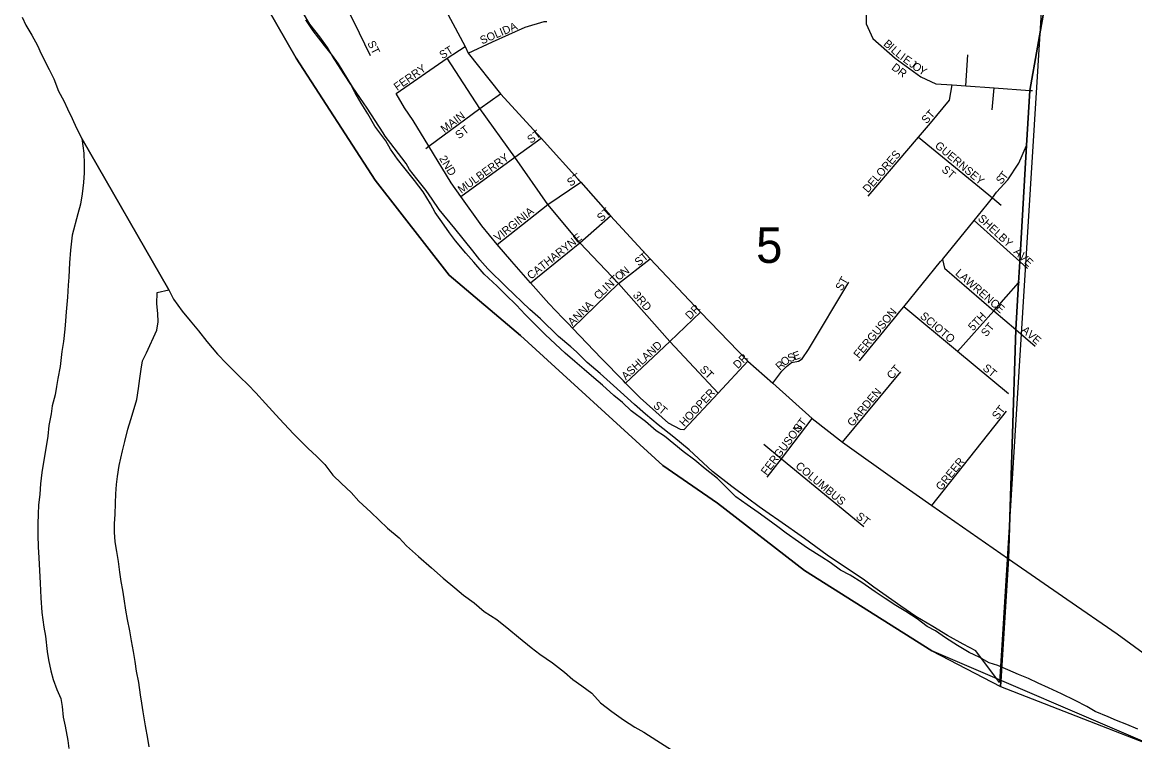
# Model space of a CAD drawing. Extents: x 1949938.81 to 1949945.61, y 152207.65 to 152214.09.
# Drawn here: x 1949940.07 to 1949941.387, y 152208.307 to 152209.158 of the extents above; entities that cross this region are included whole.
import ezdxf

# ---------------------------------------------------------------- set-up
doc = ezdxf.new("R2010")
doc.units = 0
for name, color, linetype in [('GM_X_City_Street', 7, 'Continuous'), ('GM_X_City_Street_Text', 7, 'Continuous'), ('GM_X_Corporation', 7, 'Continuous'), ('GM_X_County', 7, 'Continuous'), ('GM_X_Major_River', 7, 'Continuous'), ('GM_X_Section', 7, 'Continuous'), ('GM_X_Section_Text', 7, 'Continuous'), ('GM_X_Township', 7, 'Continuous')]:
    doc.layers.add(name, color=color, linetype=linetype)

msp = doc.modelspace()

# ---------------------------------------------------------------- linework, layer by layer
at = {"layer": 'GM_X_City_Street'}
for points in [[(1949940.4828, 152209.1185), (1949940.4627, 152209.1592), (1949940.4558, 152209.1732), (1949940.4287, 152209.2261), (1949940.4251, 152209.2332), (1949940.3975, 152209.2768), (1949940.3786, 152209.3094)], [(1949940.5424, 152209.2289), (1949940.5451, 152209.2227), (1949940.5948, 152209.1297), (1949940.5981, 152209.1219)], [(1949941.0694, 152209.1834), (1949941.0691, 152209.1566), (1949941.0772, 152209.1391), (1949941.1035, 152209.1159), (1949941.1339, 152209.0939), (1949941.1516, 152209.0857), (1949941.1711, 152209.0843), (1949941.1873, 152209.0832), (1949941.2206, 152209.0808), (1949941.2628, 152209.0777), (1949941.2661, 152209.0775)], [(1949940.5981, 152209.1219), (1949940.627, 152209.1354), (1949940.6657, 152209.1525), (1949940.6882, 152209.1592), (1949940.6913, 152209.1593)], [(1949940.5131, 152209.0739), (1949940.5732, 152209.1157), (1949940.5948, 152209.1297)], [(1949940.5981, 152209.1219), (1949940.6365, 152209.0736), (1949940.6848, 152209.0213), (1949940.7314, 152208.9693), (1949940.7666, 152208.9292), (1949940.8137, 152208.8783), (1949940.8731, 152208.8153), (1949940.9292, 152208.7573), (1949940.9589, 152208.7314), (1949941.0055, 152208.6895), (1949941.0412, 152208.6613), (1949941.1059, 152208.6151), (1949941.1469, 152208.5864), (1949941.2377, 152208.5233), (1949941.3066, 152208.4754), (1949941.3664, 152208.4347), (1949941.422, 152208.3939), (1949941.4607, 152208.3637)], [(1949940.8939, 152208.7194), (1949940.8368, 152208.7806), (1949940.776, 152208.8492), (1949940.7305, 152208.8974), (1949940.6924, 152208.9426), (1949940.6535, 152208.9988), (1949940.6119, 152209.0565), (1949940.5732, 152209.1157)], [(1949941.1873, 152209.0832), (1949941.1896, 152209.1198)], [(1949941.0715, 152208.9526), (1949941.1312, 152209.0225), (1949941.1454, 152209.0391), (1949941.1677, 152209.0662), (1949941.1711, 152209.0843)], [(1949940.7104, 152208.8083), (1949940.6938, 152208.8257), (1949940.6721, 152208.8501), (1949940.6497, 152208.8753), (1949940.6327, 152208.8955), (1949940.6142, 152208.9175), (1949940.5896, 152208.9521), (1949940.578, 152208.9684), (1949940.5518, 152209.0116), (1949940.5333, 152209.0422), (1949940.5229, 152209.0571), (1949940.5131, 152209.0739)], [(1949940.5483, 152209.009), (1949940.5518, 152209.0116), (1949940.6119, 152209.0565), (1949940.6365, 152209.0736)], [(1949941.2184, 152209.0549), (1949941.2206, 152209.0808)], [(1949940.5896, 152208.9521), (1949940.6535, 152208.9988), (1949940.6848, 152209.0213)], [(1949941.1312, 152209.0225), (1949941.2186, 152208.9506), (1949941.2291, 152208.942)], [(1949941.1582, 152208.876), (1949941.1594, 152208.8775), (1949941.197, 152208.9236), (1949941.2124, 152208.9425), (1949941.2186, 152208.9506), (1949941.2236, 152208.9572), (1949941.2371, 152208.9719), (1949941.2498, 152208.9915), (1949941.2592, 152209.0126)], [(1949940.6327, 152208.8955), (1949940.6924, 152208.9426), (1949940.7314, 152208.9693)], [(1949940.6721, 152208.8501), (1949940.7305, 152208.8974), (1949940.7666, 152208.9292)], [(1949941.197, 152208.9236), (1949941.251, 152208.8752), (1949941.26, 152208.8671)], [(1949940.7217, 152208.7964), (1949940.776, 152208.8492), (1949940.8137, 152208.8783)], [(1949941.1072, 152208.8136), (1949941.1138, 152208.8216), (1949941.1574, 152208.8751), (1949941.1582, 152208.876)], [(1949941.1594, 152208.8775), (1949941.1618, 152208.8672), (1949941.2203, 152208.817), (1949941.2462, 152208.7948), (1949941.2692, 152208.7751)], [(1949940.9589, 152208.7314), (1949940.9696, 152208.7456), (1949940.9749, 152208.7508), (1949940.9807, 152208.7555), (1949940.9893, 152208.7572), (1949940.9936, 152208.7599), (1949941.0011, 152208.7712), (1949941.0486, 152208.8506)], [(1949941.1773, 152208.7687), (1949941.2203, 152208.817), (1949941.2495, 152208.8499), (1949941.2508, 152208.8513)], [(1949941.2377, 152208.7185), (1949941.1773, 152208.7687), (1949941.1138, 152208.8216)], [(1949940.782, 152208.7338), (1949940.7559, 152208.7604), (1949940.7217, 152208.7964), (1949940.7168, 152208.8016), (1949940.7104, 152208.8083)], [(1949940.7845, 152208.7313), (1949940.8368, 152208.7806), (1949940.8731, 152208.8153)], [(1949941.0615, 152208.7575), (1949941.1063, 152208.8124), (1949941.1072, 152208.8136)], [(1949940.8535, 152208.6761), (1949940.8939, 152208.7194), (1949940.9292, 152208.7573)], [(1949941.0412, 152208.6613), (1949941.1103, 152208.7447)], [(1949940.8535, 152208.6761), (1949940.8497, 152208.6765), (1949940.8354, 152208.6839), (1949940.8016, 152208.7139), (1949940.785, 152208.7308), (1949940.7845, 152208.7313), (1949940.782, 152208.7338)], [(1949940.9521, 152208.6198), (1949940.9689, 152208.6418), (1949941.0055, 152208.6895)], [(1949941.1469, 152208.5864), (1949941.2354, 152208.6979)], [(1949940.9481, 152208.659), (1949940.9689, 152208.6418), (1949941.0663, 152208.5614)]]:
    msp.add_lwpolyline(points, dxfattribs=at)
at = {"layer": 'GM_X_Corporation'}
msp.add_lwpolyline([(1949942.1062, 152209.4059), (1949942.0896, 152209.1325), (1949942.3484, 152209.1187), (1949942.2928, 152208.2633), (1949942.1618, 152208.279), (1949942.0982, 152208.0722), (1949942.0477, 152208.0858), (1949941.8214, 152208.1567), (1949941.682, 152208.19), (1949941.6393, 152208.2075), (1949941.5072, 152208.2663), (1949941.4156, 152208.2992), (1949941.1468, 152208.4145), (1949940.9962, 152208.5094), (1949940.8932, 152208.5894), (1949940.8285, 152208.6338), (1949940.6601, 152208.7875), (1949940.5757, 152208.8589), (1949940.4882, 152208.9716), (1949940.3947, 152209.1158), (1949940.3383, 152209.2145)], dxfattribs=at)
at = {"layer": 'GM_X_County'}
msp.add_lwpolyline([(1949940.3383, 152209.2145), (1949940.3947, 152209.1158), (1949940.4882, 152208.9716), (1949940.5757, 152208.8589), (1949940.6601, 152208.7875), (1949940.8285, 152208.6338), (1949940.8932, 152208.5894), (1949940.9962, 152208.5094), (1949941.1468, 152208.4145), (1949941.2284, 152208.3724), (1949941.4156, 152208.2992), (1949941.5072, 152208.2663), (1949941.6393, 152208.2075), (1949941.682, 152208.19), (1949941.8214, 152208.1567), (1949941.9395, 152208.1188), (1949942.0477, 152208.0858), (1949942.1534, 152208.0573), (1949942.2476, 152208.0399), (1949942.3082, 152208.046), (1949942.5103, 152208.0107), (1949942.8268, 152208.0046)], dxfattribs=at)
at = {"layer": 'GM_X_Major_River'}
for p, q in [((1949940.1408, 152209.0207), (1949940.2439, 152208.8416)), ((1949940.2439, 152208.8416), (1949940.1408, 152209.0207))]:
    msp.add_line(p, q, dxfattribs=at)
for points in [[(1949940.0705, 152209.1646), (1949940.0746, 152209.1551), (1949940.0818, 152209.1433), (1949940.0886, 152209.1308), (1949940.0928, 152209.1209), (1949940.1022, 152209.1023), (1949940.1079, 152209.0913), (1949940.1135, 152209.0769), (1949940.1196, 152209.0655), (1949940.1241, 152209.056), (1949940.1294, 152209.0446), (1949940.1347, 152209.0329), (1949940.1408, 152209.0207)], [(1949940.7911, 152208.6986), (1949940.7809, 152208.7084), (1949940.7707, 152208.7168), (1949940.7571, 152208.7289), (1949940.7468, 152208.7377), (1949940.7355, 152208.7475), (1949940.7245, 152208.757), (1949940.7132, 152208.7669), (1949940.7015, 152208.7775), (1949940.6894, 152208.7889), (1949940.6773, 152208.801), (1949940.6656, 152208.8124), (1949940.6554, 152208.8234), (1949940.6425, 152208.8363), (1949940.6327, 152208.8462), (1949940.6172, 152208.8602), (1949940.6051, 152208.8746), (1949940.5956, 152208.8849), (1949940.5832, 152208.8997), (1949940.576, 152208.9092), (1949940.5669, 152208.9221), (1949940.5593, 152208.9334), (1949940.5537, 152208.9433), (1949940.545, 152208.9577), (1949940.5348, 152208.971), (1949940.5219, 152208.9869), (1949940.5147, 152208.9964), (1949940.5064, 152209.0082), (1949940.5007, 152209.0181), (1949940.4879, 152209.0355), (1949940.4796, 152209.0499), (1949940.4716, 152209.0625), (1949940.4645, 152209.075), (1949940.4592, 152209.0849), (1949940.4509, 152209.0974), (1949940.444, 152209.1084), (1949940.4376, 152209.1183), (1949940.4316, 152209.1285), (1949940.4225, 152209.141), (1949940.4108, 152209.1562), (1949940.4032, 152209.1687)], [(1949940.1408, 152209.0207), (1949940.1434, 152209.0036), (1949940.1438, 152208.9907), (1949940.1438, 152208.9801), (1949940.143, 152208.9687), (1949940.1415, 152208.9555), (1949940.1392, 152208.9429), (1949940.1362, 152208.9315), (1949940.1294, 152208.9065), (1949940.1275, 152208.8887), (1949940.1263, 152208.8735), (1949940.1256, 152208.8568), (1949940.1248, 152208.8473), (1949940.1241, 152208.8329), (1949940.1225, 152208.8158), (1949940.1218, 152208.8052), (1949940.121, 152208.7953), (1949940.1191, 152208.7805), (1949940.1172, 152208.7688), (1949940.1153, 152208.751), (1949940.1127, 152208.7369), (1949940.1108, 152208.7274), (1949940.1093, 152208.7176), (1949940.1059, 152208.7043), (1949940.1047, 152208.6948), (1949940.1021, 152208.6811), (1949940.1009, 152208.6686), (1949940.0979, 152208.6516), (1949940.0953, 152208.6352), (1949940.0938, 152208.6254), (1949940.0922, 152208.6121), (1949940.0911, 152208.6), (1949940.0896, 152208.5867), (1949940.0892, 152208.5765), (1949940.0888, 152208.5643), (1949940.0888, 152208.5514), (1949940.0892, 152208.5374), (1949940.0899, 152208.5245), (1949940.0907, 152208.5097), (1949940.0918, 152208.4945), (1949940.0926, 152208.4771), (1949940.0937, 152208.46), (1949940.096, 152208.4425), (1949940.0979, 152208.4319), (1949940.1001, 152208.4137), (1949940.1016, 152208.4039), (1949940.1043, 152208.3906), (1949940.1069, 152208.3807), (1949940.1114, 152208.3686), (1949940.116, 152208.358), (1949940.1175, 152208.3485), (1949940.119, 152208.336), (1949940.1213, 152208.3253), (1949940.1243, 152208.3083), (1949940.1254, 152208.2988)], [(1949940.2207, 152208.3007), (1949940.2192, 152208.3105), (1949940.2162, 152208.3257), (1949940.2135, 152208.3424), (1949940.212, 152208.3526), (1949940.2105, 152208.3625), (1949940.2083, 152208.3769), (1949940.2056, 152208.3902), (1949940.2041, 152208.402), (1949940.2022, 152208.4137), (1949940.1996, 152208.4262), (1949940.1977, 152208.438), (1949940.195, 152208.4516), (1949940.1932, 152208.4626), (1949940.1909, 152208.4759), (1949940.1894, 152208.4862), (1949940.1875, 152208.4964), (1949940.186, 152208.5074), (1949940.1845, 152208.5203), (1949940.1822, 152208.5321), (1949940.1803, 152208.5434), (1949940.1796, 152208.5548), (1949940.1796, 152208.5651), (1949940.1803, 152208.5757), (1949940.1807, 152208.5893), (1949940.1811, 152208.6003), (1949940.1819, 152208.6113), (1949940.183, 152208.6208), (1949940.1853, 152208.6337), (1949940.1891, 152208.6512), (1949940.1917, 152208.6622), (1949940.1955, 152208.6766), (1949940.1989, 152208.6883), (1949940.2031, 152208.7012), (1949940.2061, 152208.7119), (1949940.208, 152208.7251), (1949940.2095, 152208.7369), (1949940.211, 152208.7479), (1949940.2129, 152208.7578), (1949940.2174, 152208.7673), (1949940.2296, 152208.7938), (1949940.2314, 152208.8037), (1949940.2311, 152208.8135), (1949940.2299, 152208.8253), (1949940.2303, 152208.8386), (1949940.2439, 152208.8416)], [(1949940.2439, 152208.8416), (1949940.2496, 152208.8306), (1949940.2598, 152208.8166), (1949940.2693, 152208.8052), (1949940.2791, 152208.7931), (1949940.2889, 152208.7805), (1949940.3014, 152208.7657), (1949940.312, 152208.7544), (1949940.3279, 152208.7388), (1949940.3377, 152208.7293), (1949940.3471, 152208.7198), (1949940.3585, 152208.7073), (1949940.3751, 152208.6891), (1949940.3914, 152208.6713), (1949940.4088, 152208.6538), (1949940.4186, 152208.6447), (1949940.4284, 152208.6348), (1949940.4379, 152208.6223), (1949940.4481, 152208.6125), (1949940.4598, 152208.6018), (1949940.4689, 152208.5916), (1949940.4832, 152208.5787), (1949940.5029, 152208.5597), (1949940.5165, 152208.5483), (1949940.5252, 152208.5389), (1949940.5396, 152208.526), (1949940.5547, 152208.5127), (1949940.5687, 152208.5005), (1949940.5823, 152208.4892), (1949940.5925, 152208.4804), (1949940.6053, 152208.4713), (1949940.6171, 152208.4611), (1949940.6322, 152208.4516), (1949940.6465, 152208.4402), (1949940.6579, 152208.4307), (1949940.6726, 152208.4182), (1949940.6832, 152208.4106), (1949940.698, 152208.4004), (1949940.7123, 152208.389), (1949940.7222, 152208.3807), (1949940.7327, 152208.3731), (1949940.7445, 152208.3644), (1949940.7547, 152208.353), (1949940.7683, 152208.3427), (1949940.7819, 152208.3329), (1949940.7955, 152208.3241), (1949940.8061, 152208.3181), (1949940.8216, 152208.3082), (1949940.839, 152208.2972)], [(1949941.3907, 152208.3219), (1949941.3779, 152208.3272), (1949941.3654, 152208.3321), (1949941.3556, 152208.3363), (1949941.3404, 152208.3428), (1949941.3306, 152208.3484), (1949941.3166, 152208.3557), (1949941.3004, 152208.3636), (1949941.2852, 152208.3708), (1949941.2728, 152208.3761), (1949941.2614, 152208.3818), (1949941.2497, 152208.3864), (1949941.2368, 152208.3921), (1949941.2251, 152208.397), (1949941.2149, 152208.4004), (1949941.2028, 152208.4069), (1949941.1911, 152208.4125), (1949941.1775, 152208.4209), (1949941.1631, 152208.43), (1949941.1514, 152208.438), (1949941.1416, 152208.4433), (1949941.1298, 152208.4524), (1949941.1162, 152208.4611), (1949941.1045, 152208.4679), (1949941.0916, 152208.4763), (1949941.0799, 152208.4842), (1949941.064, 152208.4952), (1949941.0504, 152208.504), (1949941.0387, 152208.51), (1949941.0266, 152208.5191), (1949941.0168, 152208.5252), (1949940.9998, 152208.5358), (1949940.9892, 152208.5434), (1949940.9744, 152208.5537), (1949940.9646, 152208.5612), (1949940.9529, 152208.57), (1949940.9415, 152208.5783), (1949940.9283, 152208.5874), (1949940.9151, 152208.5969), (1949940.9034, 152208.6083), (1949940.8932, 152208.6185), (1949940.8788, 152208.6299), (1949940.8663, 152208.6402), (1949940.8527, 152208.6504), (1949940.8417, 152208.6595), (1949940.8304, 152208.6686), (1949940.8206, 152208.6747), (1949940.8081, 152208.6857), (1949940.7911, 152208.6986)]]:
    msp.add_lwpolyline(points, dxfattribs=at)
at = {"layer": 'GM_X_Section'}
msp.add_lwpolyline([(1949941.2772, 152209.1831), (1949941.2271, 152208.3769), (1949941.1991, 152208.4144), (1949941.1839, 152208.4224), (1949941.1657, 152208.4326), (1949941.1483, 152208.4433), (1949941.1279, 152208.455), (1949941.1104, 152208.4672), (1949941.0782, 152208.4899), (1949941.0673, 152208.4979), (1949941.0229, 152208.5278), (1949940.9964, 152208.5472), (1949940.9658, 152208.5688), (1949940.9544, 152208.5764), (1949940.9427, 152208.5847), (1949940.929, 152208.595), (1949940.9101, 152208.609), (1949940.8874, 152208.6268), (1949940.8597, 152208.6522), (1949940.8416, 152208.6674), (1949940.823, 152208.6818), (1949940.8079, 152208.6947), (1949940.795, 152208.7061), (1949940.7704, 152208.7284), (1949940.7545, 152208.7425), (1949940.7389, 152208.7557), (1949940.7265, 152208.7683), (1949940.7196, 152208.7743), (1949940.7052, 152208.7865), (1949940.6837, 152208.8073), (1949940.6712, 152208.8183), (1949940.6431, 152208.8452), (1949940.6216, 152208.8665), (1949940.6121, 152208.8771), (1949940.6038, 152208.8877), (1949940.5826, 152208.9142), (1949940.564, 152208.9366), (1949940.5557, 152208.9491), (1949940.5485, 152208.9593), (1949940.5375, 152208.973), (1949940.5288, 152208.9843), (1949940.525, 152208.9912), (1949940.5107, 152209.0097), (1949940.5, 152209.0234), (1949940.4978, 152209.0276), (1949940.4785, 152209.0568), (1949940.4614, 152209.0818), (1949940.4448, 152209.1091), (1949940.4376, 152209.1189), (1949940.4281, 152209.1307), (1949940.4149, 152209.1481), (1949940.4062, 152209.1614)], dxfattribs=at)
at = {"layer": 'GM_X_Township'}
for points in [[(1949940.3383, 152209.2145), (1949940.3947, 152209.1158), (1949940.4882, 152208.9716), (1949940.5757, 152208.8589), (1949940.6601, 152208.7875), (1949940.8285, 152208.6338), (1949940.8932, 152208.5894), (1949940.9962, 152208.5094), (1949941.1468, 152208.4145), (1949941.2284, 152208.3724), (1949941.2377, 152208.5233), (1949941.2462, 152208.7948), (1949941.2495, 152208.8499), (1949941.251, 152208.8752), (1949941.2592, 152209.0126), (1949941.2628, 152209.0777), (1949941.2812, 152209.1802)], [(1949941.2812, 152209.1802), (1949941.2628, 152209.0777), (1949941.2592, 152209.0126), (1949941.251, 152208.8752), (1949941.2495, 152208.8499), (1949941.2462, 152208.7948), (1949941.2377, 152208.5233), (1949941.2284, 152208.3724), (1949941.4156, 152208.2992), (1949941.5072, 152208.2663), (1949941.6393, 152208.2075), (1949941.682, 152208.19), (1949941.8214, 152208.1567), (1949941.9395, 152208.1188), (1949942.0477, 152208.0858), (1949942.1534, 152208.0573), (1949942.2476, 152208.0399), (1949942.3082, 152208.046), (1949942.5103, 152208.0107), (1949942.8268, 152208.0046)]]:
    msp.add_lwpolyline(points, dxfattribs=at)

# ---------------------------------------------------------------- texts
at = {"layer": 'GM_X_City_Street_Text'}
for s, rotation, p in [('SOLIDA', 23.0516, (1949940.6146, 152209.1321)), ('ST', 296.5647, (1949940.4786, 152209.1338)), ('B', 318.2418, (1949941.089, 152209.1318)), ('ST', 31.6151, (1949940.5677, 152209.1145)), ('I', 318.2507, (1949941.0946, 152209.1268)), ('L', 318.3975, (1949941.0977, 152209.124)), ('L', 321.1059, (1949941.1031, 152209.1193)), ('I', 323.045, (1949941.1085, 152209.1149)), ('FERRY', 35.094, (1949940.5143, 152209.0769)), ('DR', 323.1345, (1949941.0984, 152209.1032)), ('E', 323.9242, (1949941.112, 152209.1123)), ('J', 323.8995, (1949941.1194, 152209.1069)), ('O', 323.912, (1949941.1228, 152209.1044)), ('Y', 329.331, (1949941.1303, 152209.099)), ('ST', 47.4955, (1949941.1406, 152209.0375)), ('MAIN', 37.1854, (1949940.5701, 152209.0269)), ('ST', 36.867, (1949940.5873, 152209.0197)), ('ST', 37.5756, (1949940.6725, 152209.0144)), ('GUERNSEY', 319.8986, (1949941.1498, 152209.011)), ('MULBERRY', 35.5378, (1949940.5901, 152208.9553)), ('DELORES', 49.4994, (1949941.0714, 152208.9558)), ('2ND', 301.3286, (1949940.5635, 152208.9972)), ('ST', 34.6943, (1949940.7193, 152208.9636)), ('ST', 320.1969, (1949941.1577, 152208.9827)), ('S', 49.2061, (1949941.229, 152208.9659)), ('T', 52.6796, (1949941.2337, 152208.9714)), ('VIRGINIA', 38.5169, (1949940.6334, 152208.8985)), ('ST', 42.5078, (1949940.7558, 152208.9218)), ('SHELBY', 317.2319, (1949941.2007, 152208.9251)), ('CATHARYNE', 38.3466, (1949940.6725, 152208.8535)), ('ST', 39.8121, (1949940.8, 152208.8693)), ('A', 315.0724, (1949941.2432, 152208.8859)), ('V', 316.2898, (1949941.2493, 152208.8799)), ('E', 317.6715, (1949941.2555, 152208.8739)), ('T', 41.8864, (1949940.7716, 152208.8477)), ('O', 38.7737, (1949940.7764, 152208.852)), ('N', 38.284, (1949940.7829, 152208.8572)), ('ST', 60.2572, (1949941.0404, 152208.8397)), ('LAWRENCE', 319.2357, (1949941.174, 152208.8602)), ('I', 43.8852, (1949940.7626, 152208.8391)), ('N', 43.8699, (1949940.7656, 152208.842)), ('C', 43.8704, (1949940.7524, 152208.8293)), ('L', 43.8793, (1949940.7578, 152208.8345)), ('3RD', 310.3617, (1949940.7925, 152208.835)), ('ANNA', 43.9956, (1949940.7216, 152208.7984)), ('DR', 44.9989, (1949940.8607, 152208.8059)), ('FERGUSON', 50.6008, (1949941.0606, 152208.7599)), ('SCIOTO', 319.8978, (1949941.1323, 152208.8093)), ('5TH', 46.6395, (1949941.1957, 152208.7925)), ('ST', 50.1994, (1949941.2114, 152208.7854)), ('AVE', 319.1889, (1949941.2523, 152208.7927)), ('ASHLAND', 43.1522, (1949940.7849, 152208.7343)), ('DR', 44.9989, (1949940.9174, 152208.7476)), ('S', 20.5768, (1949940.9783, 152208.7558)), ('E', 19.6189, (1949940.9845, 152208.7581)), ('R', 43.0854, (1949940.9673, 152208.7458)), ('O', 40.0672, (1949940.9727, 152208.7509)), ('CT', 49.7596, (1949941.0998, 152208.735)), ('ST', 320.1969, (1949941.2064, 152208.7477)), ('ST', 314.9941, (1949940.8716, 152208.7467)), ('HOOPER', 47.1761, (1949940.854, 152208.6792)), ('GARDEN', 49.9373, (1949941.0531, 152208.6791)), ('ST', 320.1969, (1949940.8164, 152208.7035)), ('ST', 52.4361, (1949941.2247, 152208.6874)), ('ST', 52.4255, (1949940.9897, 152208.6724)), ('FERGUSON', 52.8165, (1949940.9513, 152208.6215)), ('COLUMBUS', 320.291, (1949940.9848, 152208.6318)), ('GREER', 51.1473, (1949941.1581, 152208.6033)), ('ST', 322.4244, (1949941.0564, 152208.5719))]:
    msp.add_text(s, height=0.00947, rotation=rotation, dxfattribs=at).set_placement(p)
at = {"layer": 'GM_X_Section_Text'}
msp.add_text('5', height=0.0419, rotation=0, dxfattribs=at).set_placement((1949940.939, 152208.8736))

doc.saveas('drawing.dxf')
